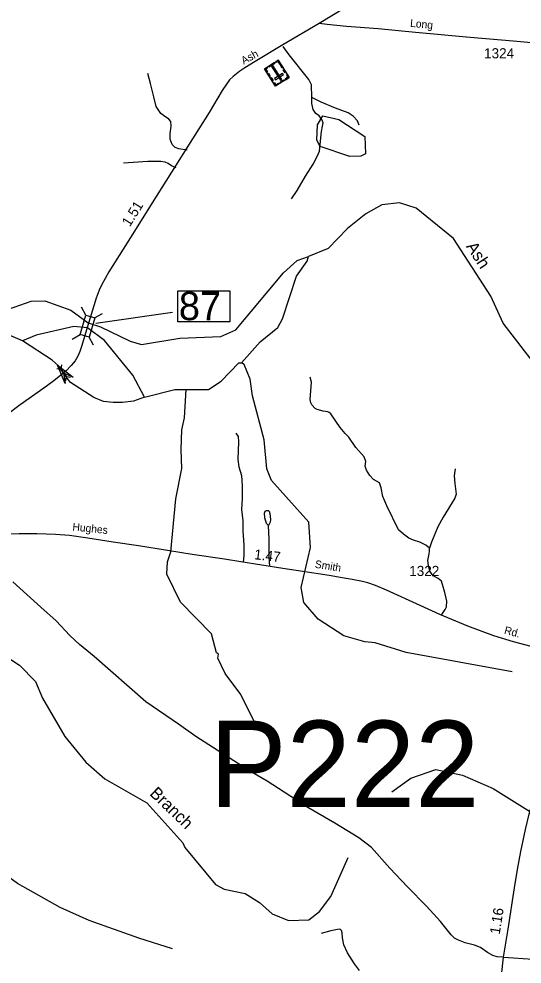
# Model space of a CAD drawing. Extents: x 2104537 to 2336408, y 34176 to 229611.
# Drawn here: x 2135763 to 2141974, y 100551 to 112212 of the extents above; entities that cross this region are included whole.
import ezdxf

# ---------------------------------------------------------------- set-up
doc = ezdxf.new("R2010")
doc.units = 0
for name, color, linetype in [('Exist Cultural Cemetery CELL', 7, 'Continuous'), ('Exist Hydrographic Creek Single Shore', 7, 'Continuous'), ('Exist Hydrographic Misc Water Feature', 7, 'Continuous'), ('Exist Hydrographic Pond Under 1500 Sq Ft', 7, 'Continuous'), ('Exist Road Non-System Type 51', 7, 'Continuous'), ('Exist Road Secondary Mileage Hundredths English Label', 7, 'Continuous'), ('Exist Road Secondary Structure Pipe Attributed CELL', 7, 'Continuous'), ('Exist Road Secondary Structure Pipe CELL', 7, 'Continuous'), ('Exist Road Secondary Structure Pipe Number Label', 7, 'Continuous'), ('Exist Road Secondary Structure Standard Bridge CELL', 7, 'Continuous'), ('Exist Road Secondary Structure Standard Bridge Number Label', 7, 'Continuous'), ('Exist Road Secondary Type 51 Attributed', 7, 'Continuous'), ('Exist Road Secondary Type 51 Label', 7, 'Continuous'), ('Exist Road Secondary Type 51 Number Label', 7, 'Continuous'), ('Old_Level_32', 7, 'Continuous')]:
    doc.layers.add(name, color=color, linetype=linetype)

msp = doc.modelspace()

# ---------------------------------------------------------------- linework, layer by layer
at = {"layer": 'Exist Cultural Cemetery CELL'}
for points in [[(2139099, 111489), (2138930, 111382), (2138794, 111597), (2138962, 111704)], [(2138822, 111615), (2138828, 111605), (2138810, 111593), (2138831, 111559), (2138822, 111553), (2138794, 111597)], [(2138920, 111663), (2138848, 111618), (2138842, 111627), (2138914, 111673)], [(2138991, 111455), (2139007, 111465), (2138898, 111636), (2138882, 111626)], [(2138934, 111686), (2138941, 111676), (2138959, 111688), (2138981, 111654), (2138990, 111660), (2138962, 111704)], [(2139000, 111645), (2139023, 111608), (2139013, 111602), (2138990, 111639)], [(2138842, 111542), (2138866, 111506), (2138856, 111500), (2138833, 111536)], [(2138878, 111487), (2138901, 111450), (2138891, 111444), (2138868, 111480)], [(2139028, 111524), (2139018, 111540), (2138918, 111477), (2138928, 111461)], [(2139036, 111588), (2139059, 111551), (2139049, 111545), (2139026, 111582)], [(2139075, 111525), (2139066, 111519), (2139083, 111492), (2139049, 111470), (2139055, 111461), (2139099, 111489)], [(2138907, 111419), (2138917, 111425), (2138934, 111398), (2138968, 111419), (2138974, 111410), (2138930, 111382)], [(2139036, 111449), (2138992, 111421), (2138986, 111431), (2139030, 111459)]]:
    msp.add_lwpolyline(points, close=True, dxfattribs=at)
at = {"layer": 'Exist Hydrographic Creek Single Shore'}
for points in [[(2142671, 107118), (2142478, 107368), (2142336, 107686), (2141741, 108459), (2141589, 108790), (2141128, 109504), (2140668, 109877), (2140459, 109944), (2140243, 109918), (2140043, 109807), (2139819, 109625), (2139578, 109380), (2139337, 109280)], [(2138510, 107967), (2138742, 108228), (2138958, 108404), (2139016, 108511), (2139188, 109036), (2139320, 109221), (2139337, 109280)], [(2135809, 108239), (2135633, 108315), (2135416, 108463), (2135382, 108513)], [(2137312, 107547), (2137179, 107494), (2137043, 107478), (2136926, 107478), (2136807, 107493), (2136687, 107541), (2136401, 107728), (2136352, 107791), (2136249, 107936), (2136173, 108001), (2135809, 108239)], [(2137827, 107639), (2138102, 107640), (2138261, 107742), (2138476, 107967), (2138510, 107967)], [(2137312, 107547), (2137686, 107638), (2137827, 107639)], [(2135459, 104440), (2135768, 104240), (2135968, 104039), (2136053, 103831), (2136330, 103360), (2136590, 103043), (2136824, 102835), (2137342, 102540), (2137786, 102049), (2137811, 101989), (2138188, 101532), (2138297, 101474), (2138555, 101420), (2138731, 101312), (2138890, 101171), (2139090, 101088), (2139340, 101097), (2139473, 101199), (2139614, 101383), (2139828, 101865)]]:
    msp.add_lwpolyline(points, dxfattribs=at)
at = {"layer": 'Exist Hydrographic Misc Water Feature'}
for points in [[(2135382, 108513), (2135491, 108580), (2135913, 108729), (2136081, 108735), (2136405, 108617), (2136616, 108461), (2136771, 108412), (2137134, 108236), (2137275, 108194), (2137750, 108274), (2138257, 108293), (2138441, 108375), (2139030, 109079), (2139196, 109230), (2139337, 109280)], [(2137312, 107547), (2137169, 107815), (2136821, 108244), (2136610, 108399), (2136442, 108418), (2135974, 108308), (2135809, 108239)], [(2141851, 104158), (2140542, 104394), (2140158, 104516), (2140033, 104525), (2139775, 104599), (2139457, 104805), (2139281, 105012), (2139247, 105196), (2139361, 105690), (2139343, 106005), (2138882, 106519), (2138824, 106661), (2138789, 107020), (2138645, 107561), (2138619, 107768), (2138543, 107950), (2138510, 107967)], [(2138671, 103534), (2138503, 103875), (2138310, 104135), (2138217, 104324), (2138226, 104376), (2138200, 104393), (2138141, 104624), (2137756, 105015), (2137588, 105363), (2137596, 105514), (2137637, 105638), (2137701, 106290), (2137774, 106665), (2137765, 106899), (2137772, 107141), (2137805, 107291), (2137827, 107639)], [(2140366, 102678), (2140599, 102844), (2140907, 102953), (2141240, 102881), (2141616, 102716), (2142176, 102367), (2142334, 102335), (2142584, 102385), (2142733, 102471), (2142957, 102713), (2143090, 102763), (2143215, 102813), (2143398, 103023), (2143676, 104041), (2143974, 104626)], [(2137658, 100739), (2137241, 100872), (2136632, 101087), (2136273, 101251), (2135747, 101547), (2135070, 102036), (2134116, 102674), (2133741, 102790), (2133523, 102965), (2133305, 103320), (2133180, 103421), (2132687, 103683), (2132495, 103858), (2132286, 104108)]]:
    msp.add_lwpolyline(points, dxfattribs=at)
at = {"layer": 'Exist Hydrographic Pond Under 1500 Sq Ft'}
msp.add_lwpolyline([(2139848, 110516), (2139481, 110638), (2139439, 110715), (2139447, 110905), (2139513, 111015), (2139713, 110972), (2140031, 110759), (2140040, 110549), (2139982, 110517), (2139848, 110516)], dxfattribs=at)
at = {"layer": 'Exist Road Non-System Type 51'}
for points in [[(2139377, 111241), (2139376, 111399), (2139341, 111463), (2139097, 111767), (2139024, 111870)], [(2137838, 110594), (2137737, 110607), (2137691, 110625), (2137653, 110664), (2137628, 110726), (2137628, 110796), (2137641, 110890), (2137637, 110944), (2137614, 110976), (2137548, 111019), (2137514, 111045), (2137457, 111131), (2137430, 111252), (2137389, 111414), (2137353, 111538)], [(2139128, 109991), (2139197, 110096), (2139302, 110273), (2139394, 110419), (2139449, 110522), (2139473, 110580), (2139497, 110824), (2139512, 110890), (2139518, 110930), (2139503, 110970), (2139467, 111014), (2139429, 111044), (2139396, 111095), (2139380, 111167), (2139377, 111241)], [(2139964, 110902), (2139940, 110956), (2139889, 111012), (2139825, 111051), (2139672, 111110), (2139494, 111186), (2139377, 111241)], [(2137702, 110375), (2137647, 110398), (2137605, 110428), (2137569, 110444), (2137515, 110453), (2137353, 110451), (2137053, 110433)], [(2140829, 105683), (2140785, 105720), (2140711, 105758), (2140633, 105781), (2140576, 105805), (2140508, 105854), (2140450, 105910), (2140303, 106206), (2140254, 106320), (2140235, 106428), (2140215, 106487), (2140140, 106529), (2140096, 106578), (2140055, 106644), (2140037, 106694), (2140046, 106750), (2140026, 106808), (2139923, 106925), (2139836, 107050), (2139789, 107096), (2139727, 107171), (2139612, 107340), (2139593, 107356), (2139576, 107364), (2139519, 107373), (2139445, 107395), (2139420, 107407), (2139378, 107449), (2139366, 107476), (2139357, 107515), (2139374, 107730), (2139357, 107790)], [(2138441, 107102), (2138468, 107060), (2138472, 106994), (2138466, 106776), (2138479, 106686), (2138512, 106579), (2138517, 106453), (2138519, 106293), (2138512, 106161), (2138527, 106021), (2138528, 105897), (2138539, 105719), (2138539, 105589), (2138531, 105511)], [(2141149, 106659), (2141134, 106573), (2141142, 106479), (2141160, 106350), (2141142, 106299), (2140998, 106066), (2140935, 105944), (2140857, 105757), (2140829, 105683)], [(2138843, 105960), (2138819, 105987), (2138797, 106055), (2138794, 106115), (2138802, 106139), (2138818, 106147), (2138838, 106149), (2138850, 106138), (2138860, 106110), (2138866, 106072), (2138869, 106034), (2138865, 106002), (2138843, 105960)], [(2138858, 105458), (2138853, 105576), (2138851, 105792), (2138843, 105960)], [(2140983, 104864), (2141022, 104925), (2141040, 104959), (2141043, 105027), (2141018, 105137), (2140991, 105236), (2140977, 105274), (2140937, 105308), (2140877, 105339), (2140834, 105399), (2140817, 105467), (2140809, 105531), (2140826, 105611), (2140830, 105645), (2140829, 105683)], [(2141745, 100638), (2141665, 100641), (2141613, 100657), (2141547, 100696), (2141460, 100757), (2141386, 100783), (2141270, 100812), (2141190, 100845), (2141141, 100871), (2141097, 100914), (2140966, 101077), (2140794, 101266), (2140558, 101503), (2140342, 101736), (2140114, 101989), (2139957, 102110), (2139663, 102290), (2139330, 102485), (2138825, 102808), (2138620, 102927), (2137946, 103359), (2137733, 103509), (2137328, 103787), (2136690, 104347), (2136510, 104494), (2136391, 104603), (2136224, 104787), (2136034, 104954), (2135686, 105267)], [(2139965, 100473), (2139904, 100554), (2139817, 100691), (2139772, 100789), (2139756, 100875), (2139751, 100937), (2139745, 100967), (2139733, 100977), (2139717, 100980), (2139611, 100963), (2139495, 100930)], [(2141745, 100638), (2142110, 100613), (2142682, 100542), (2143225, 100485), (2143323, 100469), (2143383, 100468), (2143410, 100458), (2143433, 100440), (2143457, 100410), (2143469, 100379), (2143478, 100299), (2143504, 100230), (2143561, 100168), (2143606, 100062), (2143639, 99994), (2143685, 99959), (2143745, 99935), (2143806, 99882), (2143984, 99795), (2144083, 99754)]]:
    msp.add_lwpolyline(points, dxfattribs=at)
at = {"layer": 'Exist Road Secondary Structure Pipe Attributed CELL'}
msp.add_lwpolyline([(2136333, 107715), (2136241, 107941), (2136433, 107791), (2136315, 107843)], close=True, dxfattribs=at)
at = {"layer": 'Exist Road Secondary Structure Pipe CELL'}
for p, q in [((2136229, 107899), (2136279, 107892)), ((2136288, 107942), (2136279, 107892)), ((2136279, 107892), (2136350, 107795)), ((2136341, 107745), (2136350, 107795)), ((2136401, 107788), (2136350, 107795))]:
    msp.add_line(p, q, dxfattribs=at)
at = {"layer": 'Exist Road Secondary Structure Standard Bridge CELL'}
for p, q in [((2136589, 108555), (2136534, 108654)), ((2136697, 108523), (2136796, 108578)), ((2136420, 108262), (2136519, 108317)), ((2136685, 108185), (2136631, 108284))]:
    msp.add_line(p, q, dxfattribs=at)
msp.add_lwpolyline([(2136519, 108317), (2136588, 108555), (2136699, 108523), (2136631, 108284)], close=True, dxfattribs=at)
at = {"layer": 'Exist Road Secondary Structure Standard Bridge Number Label'}
msp.add_line((2136712, 108458), (2137657, 108595), dxfattribs=at)
msp.add_lwpolyline([(2137724, 108857), (2138368, 108857), (2138368, 108475), (2137724, 108475)], close=True, dxfattribs=at)
at = {"layer": 'Exist Road Secondary Type 51 Attributed'}
for points in [[(2143463, 115582), (2143262, 115423), (2142952, 115174), (2142789, 115037), (2142675, 114946), (2142601, 114867), (2142533, 114782), (2142437, 114649), (2142264, 114380), (2142010, 113987), (2141948, 113872), (2141842, 113714), (2141773, 113608), (2141734, 113567), (2141669, 113519), (2141545, 113431), (2141360, 113314), (2141024, 113106), (2140707, 112910), (2140406, 112719), (2140220, 112598), (2140043, 112495), (2139781, 112343), (2139469, 112153)], [(2139469, 112153), (2139019, 111891), (2138680, 111685), (2138550, 111607), (2138490, 111566), (2138449, 111532), (2138407, 111500), (2138362, 111460), (2138323, 111406), (2138271, 111327), (2138111, 111058), (2137858, 110654), (2137696, 110397), (2137408, 109943), (2137231, 109660), (2137050, 109371), (2136874, 109092), (2136781, 108927), (2136753, 108867), (2136716, 108767), (2136595, 108376)], [(2145003, 111652), (2144634, 111682), (2144129, 111730), (2143465, 111788), (2142884, 111842), (2142320, 111894), (2141865, 111937), (2141332, 111982), (2140657, 112045), (2140198, 112088), (2139807, 112119), (2139569, 112143), (2139469, 112153)], [(2136595, 108376), (2136541, 108184), (2136513, 108108), (2136491, 108052), (2136459, 107992), (2136409, 107935), (2136347, 107871), (2136315, 107843)], [(2136315, 107843), (2136282, 107816), (2136193, 107745), (2136072, 107655), (2135780, 107451), (2135594, 107311), (2135523, 107250), (2135479, 107203), (2135443, 107155), (2135410, 107099), (2135374, 107021), (2135326, 106855), (2135246, 106569), (2135207, 106403), (2135090, 106012), (2135043, 105848)], [(2142146, 104453), (2141867, 104527), (2141623, 104600), (2141302, 104722), (2140960, 104866), (2140714, 104977), (2140298, 105165), (2140164, 105221), (2140071, 105253), (2140002, 105271), (2139875, 105296), (2139754, 105316), (2139592, 105344), (2139267, 105394), (2139020, 105431), (2138504, 105515), (2138300, 105545), (2137903, 105606), (2137595, 105653), (2137237, 105711), (2136927, 105757), (2136614, 105807), (2136389, 105839), (2136214, 105852), (2135986, 105859), (2135767, 105859), (2135339, 105852)], [(2141200, 98379), (2141247, 98475), (2141346, 98678), (2141411, 98817), (2141456, 98940), (2141491, 99078), (2141528, 99256), (2141567, 99487), (2141621, 99781), (2141665, 100060), (2141718, 100409), (2141745, 100638), (2141802, 100980), (2141880, 101493), (2141915, 101720), (2141956, 101940), (2142014, 102212), (2142062, 102402), (2142127, 102625), (2142207, 102921), (2142367, 103492), (2142501, 103984), (2142601, 104343)]]:
    msp.add_lwpolyline(points, dxfattribs=at)

# ---------------------------------------------------------------- texts
at = {"layer": 'Exist Road Secondary Mileage Hundredths English Label'}
for s, rotation, p in [('1.51', 57.9731, (2137131, 109639)), ('1.47', 353.7042, (2138662, 105546)), ('1.16', 81.152, (2141697, 100913))]:
    msp.add_text(s, height=125, rotation=rotation, dxfattribs=at).set_placement(p)
at = {"layer": 'Exist Road Secondary Structure Pipe Number Label'}
msp.add_text('P222', height=1066.3, dxfattribs=at).set_placement((2138116, 102488))
at = {"layer": 'Exist Road Secondary Structure Standard Bridge Number Label'}
msp.add_text('87', height=350, dxfattribs=at).set_placement((2137737, 108495))
at = {"layer": 'Exist Road Secondary Type 51 Label'}
for s, rotation, p in [('Long', 354.4417, (2140588, 112115)), ('Ash', 28.8671, (2138537, 111647)), ('Hughes ', 354.2264, (2136420, 105901)), ('Smith', 350.799, (2139411, 105442)), ('Rd.', 344.9792, (2141746, 104629))]:
    msp.add_text(s, height=95, rotation=rotation, dxfattribs=at).set_placement(p)
at = {"layer": 'Exist Road Secondary Type 51 Number Label'}
for s, p in [('1324', (2141504, 111725)), ('1322', (2140580, 105339))]:
    msp.add_text(s, height=125, dxfattribs=at).set_placement(p)
at = {"layer": 'Old_Level_32'}
for s, rotation, p in [('Ash', 302.832, (2141277, 109405)), ('Branch', 316.2588, (2137367, 102644))]:
    msp.add_text(s, height=150, rotation=rotation, dxfattribs=at).set_placement(p)

doc.saveas('drawing.dxf')
